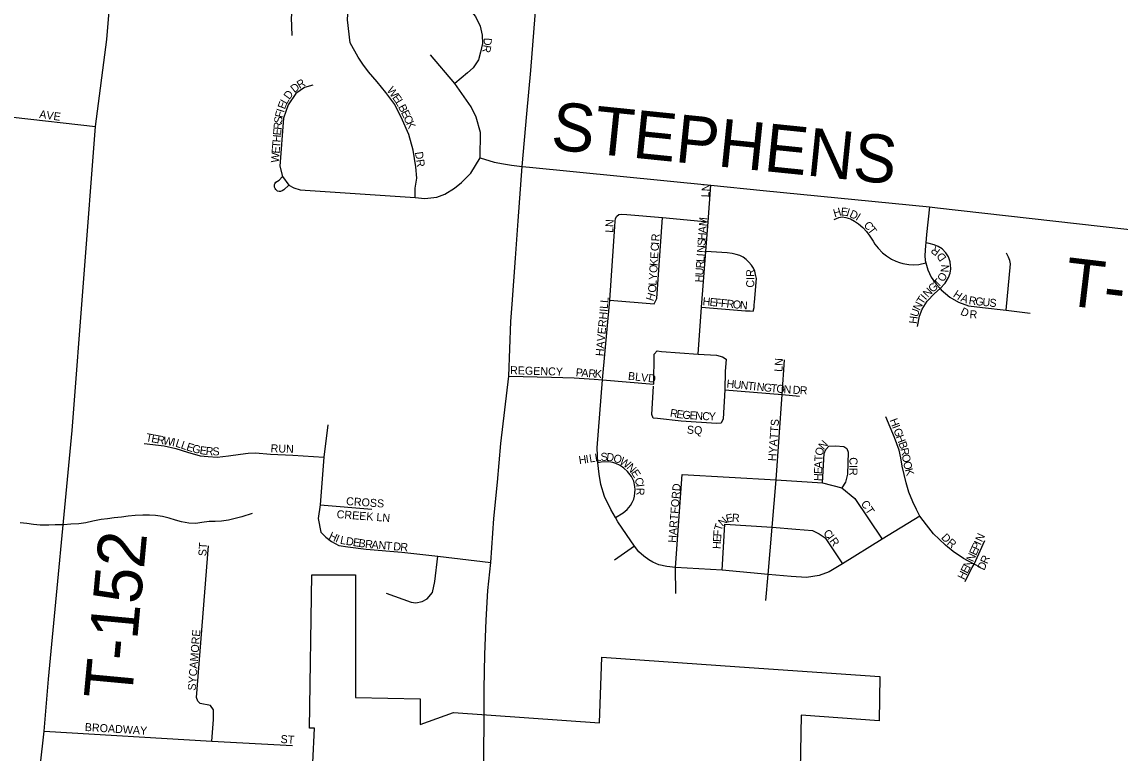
# Model space of a CAD drawing. Extents: x 1310247 to 1664935, y 284496 to 704931.
# Drawn here: x 1478771 to 1485632, y 484550 to 489120 of the extents above; entities that cross this region are included whole.
import ezdxf

# ---------------------------------------------------------------- set-up
doc = ezdxf.new("R2010")
doc.units = 0
for name, color, linetype in [('GM_P_State_Location', 7, 'Continuous'), ('GM_X_County_Subdivision_Text', 7, 'Continuous'), ('GM_X_Interstate_Shield', 7, 'Continuous'), ('GM_X_Major_Lake_Text', 7, 'Continuous'), ('GM_X_Minor_River_Text', 7, 'Continuous'), ('GM_X_State_Location', 7, 'Continuous'), ('GM_X_Township_Subdivision', 7, 'Continuous')]:
    doc.layers.add(name, color=color, linetype=linetype)

msp = doc.modelspace()

# ---------------------------------------------------------------- linework, layer by layer
at = {"layer": 'GM_X_County_Subdivision_Text'}
for points in [[(1478833.3, 483998.3), (1478911, 484686.8), (1478938.3, 485012.2), (1479085.4, 486565.2), (1479231.6, 488465.5), (1479301.4, 489011), (1479426.1, 490533.8)], [(1481634.8, 488270.5), (1481721.4, 488243), (1481779.5, 488232.1), (1481830.6, 488224.3), (1481896.7, 488216.2), (1481943.2, 488211.6)], [(1481943.2, 488211.6), (1483076.1, 488099.3), (1483402.3, 488067), (1484440.5, 487963.4), (1484490.8, 487958.4), (1485951.9, 487794.1), (1487377.7, 487632.8), (1488308.9, 487514.3), (1488786, 487462.6), (1489091.2, 487425.6)]]:
    msp.add_lwpolyline(points, dxfattribs=at)
at = {"layer": 'GM_X_Interstate_Shield'}
for points in [[(1481659.7, 484891.5), (1481659.8, 484951.8), (1481662.9, 485164.8), (1481672.3, 485380.9), (1481681.7, 485565.7), (1481700.5, 485741), (1481719.3, 486016.6), (1481743, 486242.3), (1481763.1, 486485.5), (1481812.3, 486906.5), (1481825.2, 487247.2), (1481835, 487356.5), (1481855.1, 487642.7), (1481871.5, 487875.9), (1481896.7, 488216.2), (1481925, 488546), (1481950.6, 488816.5), (1481984.1, 489239.5), (1482017.5, 489654.7), (1482052.9, 490048.2), (1482082.4, 490422.1), (1482102.1, 490668), (1482120.2, 490899.8)], [(1481860.4, 482849.6), (1481832.6, 482959.1), (1481766.5, 483237.6), (1481718.3, 483443.3), (1481689.4, 483591.1), (1481656.8, 483791.7), (1481652.6, 483885.5), (1481656.5, 484008.2), (1481654, 484367.2), (1481659.7, 484743.8), (1481659.7, 484891.5)]]:
    msp.add_lwpolyline(points, dxfattribs=at)
at = {"layer": 'GM_X_Major_Lake_Text'}
msp.add_lwpolyline([(1480588.6, 484489), (1480598.2, 484705.9), (1480567, 484705.9), (1480581.8, 485664), (1480854.8, 485664), (1480855, 484896.1), (1481258.3, 484889), (1481258.3, 484728.3), (1481466.6, 484802.7), (1482380.1, 484737.4), (1482394.4, 485149), (1483254.3, 485088.8), (1484131.2, 485027.5), (1484126.4, 484751.6), (1483638.6, 484785.7), (1483624.9, 483988.8)], dxfattribs=at)
at = {"layer": 'GM_X_Minor_River_Text'}
msp.add_lwpolyline([(1480209.9, 486047.8), (1480145.3, 486026.8), (1480103, 486015.5), (1480062.8, 486006.1), (1480018.5, 485998.8), (1479978.3, 485997.4), (1479940.2, 485996), (1479896, 485990.7), (1479857.8, 485985.3), (1479813.6, 485986), (1479767.7, 485994.7), (1479729.7, 486005.4), (1479691.8, 486018), (1479649.8, 486028.7), (1479605.8, 486035.4), (1479567.7, 486036), (1479525.6, 486036.7), (1479479.4, 486035.4), (1479435.2, 486030.1), (1479393, 486024.8), (1479346.8, 486019.5), (1479306.5, 486014.1), (1479266.3, 486008.7), (1479214, 485999.5), (1479169.7, 485988.2), (1479127.5, 485982.9), (1479077.3, 485979.7), (1479033.1, 485976.4), (1478978.9, 485975.2), (1478938.7, 485973.8), (1478884.6, 485974.7), (1478844.5, 485977.4), (1478802.5, 485984), (1478760.4, 485988.7)], dxfattribs=at)
at = {"layer": 'GM_X_State_Location'}
for points in [[(1480459.2, 489035.9), (1480456.2, 489148.1), (1480463.1, 489203.2), (1480467.1, 489264.1), (1480480.8, 489315.3), (1480507.4, 489358.6), (1480542.8, 489393), (1480586.1, 489411.7), (1480632.3, 489419.6), (1480688.4, 489417.6), (1480822.2, 489405.8), (1481266.9, 489374.3), (1481362.3, 489351.7), (1481434.1, 489313.3), (1481548.3, 489220.9), (1481604.3, 489154), (1481633.8, 489093.9), (1481646.6, 489036.9), (1481649.6, 488984.8), (1481636.8, 488930.6), (1481623, 488883.4), (1481589.6, 488833.2), (1481555.1, 488802.3), (1481475.4, 488735.8)], [(1481228.5, 488021.6), (1481228.5, 488080.5), (1481237.4, 488143.6), (1481231.5, 488214.4), (1481214.7, 488318.7), (1481188.2, 488416.1), (1481148.8, 488506.6), (1481100.6, 488603), (1481045.5, 488679.8), (1480990.4, 488745.7), (1480936.3, 488808.6), (1480901.9, 488855.9), (1480872.4, 488899.2), (1480822.2, 488989.7), (1480805.5, 489132.3), (1480822.2, 489405.8)], [(1480589.6, 488724.9), (1480535.7, 488709.2), (1480483, 488672.2), (1480433.7, 488601.5), (1480405.6, 488518.5), (1480383.2, 488217.9), (1480400, 488152.8), (1480439.3, 488099.5), (1480469, 488082.7), (1480509.9, 488069.8), (1481228.5, 488021.6), (1481288.5, 488015.7), (1481362.3, 488025.5), (1481413.5, 488044.2), (1481474.5, 488079.7), (1481517.7, 488116.1), (1481574.8, 488175.1), (1481634.8, 488270.5), (1481636.8, 488427.9), (1481608.3, 488524.3), (1481576.8, 488590.2), (1481475.4, 488735.8), (1481323.9, 488913.9)], [(1476895.4, 488497.4), (1476979.1, 488485.8), (1477070.9, 488505.3), (1477149.1, 488556.1), (1477237.1, 488585.5), (1477332.8, 488601.1), (1477432.5, 488608.9), (1477528.3, 488620.6), (1477602.6, 488638.2), (1477702.2, 488653.9), (1477823.4, 488655.8), (1478226, 488591.3), (1478717, 488524.3), (1479231.6, 488465.5)], [(1480439.3, 488099.5), (1480406.7, 488070.9), (1480397.2, 488064.1), (1480387.1, 488060.8), (1480378.1, 488060.8), (1480368.6, 488063), (1480363.5, 488066.4), (1480357.4, 488072), (1480352.9, 488078.2), (1480349.5, 488086), (1480349.5, 488095), (1480349.5, 488103.4), (1480350.6, 488108.5), (1480358.5, 488117.5), (1480378.1, 488131.5), (1480400, 488152.8)], [(1482995.3, 487044), (1483017.7, 487335.9), (1483044.4, 487684.4), (1483058.7, 487871.1), (1483076.1, 488099.3)], [(1484440.5, 487963.4), (1484422.9, 487790.5), (1484417.6, 487738.2), (1484416.1, 487723.3), (1484412.2, 487658.9), (1484415.1, 487628.7), (1484418, 487613.1), (1484430.7, 487570.2), (1484451.1, 487523.5), (1484483.3, 487480.6), (1484507, 487453.2), (1484514.5, 487444.5), (1484568.1, 487398.7), (1484622.7, 487367.5), (1484685.1, 487346.1), (1484771.8, 487335.3), (1484920.5, 487317.8), (1485069.1, 487300.3)], [(1484381.5, 486030), (1484146.4, 485887.4), (1483898.1, 485731.6), (1483815, 485682.6), (1483752.7, 485659), (1483673.4, 485647.6), (1483576.1, 485654.2), (1483433.1, 485666.5), (1483145.6, 485693), (1482854.9, 485710.4), (1482799.6, 485716.5), (1482749.6, 485726), (1482712.3, 485742.1), (1482687.2, 485757.1), (1482655.6, 485780.3), (1482624.9, 485808.1), (1482597.5, 485842.6), (1482548.2, 485915.2), (1482494.1, 485994.1), (1482479.1, 486021.5), (1482450.3, 486071.5), (1482411.5, 486154.1), (1482387, 486227.8), (1482377.5, 486292), (1482369.1, 486364.3), (1482364.4, 486458.1), (1482399.3, 486882), (1482443.2, 487379.7), (1482475, 487841.7), (1482477.2, 487873.5), (1482480, 487891.9), (1482487, 487904.8), (1482500.3, 487915.1), (1482519.4, 487918.8), (1482549.9, 487916.3), (1482772.4, 487898.4), (1483058.7, 487871.1)], [(1482443.2, 487379.7), (1482721.1, 487357.8), (1482737.3, 487390.1), (1482772.4, 487898.4)], [(1483845.9, 487885.4), (1483875.6, 487897.2), (1483895.9, 487901.4), (1483919.2, 487898.2), (1483946.9, 487889.7), (1483973.5, 487874.8), (1483996.9, 487857.8), (1484025.6, 487834.4), (1484048, 487809.9), (1484069.2, 487780.1), (1484088.4, 487749.3), (1484100.1, 487731.2), (1484120.3, 487706.7), (1484148, 487676.9), (1484172.4, 487656.7), (1484203.3, 487637.6), (1484230.9, 487623.8), (1484254.3, 487615.3), (1484275.6, 487608.9), (1484311.8, 487603.6), (1484339.4, 487601.4), (1484374.5, 487604.6), (1484418, 487613.1)], [(1483017.7, 487335.9), (1483291, 487313.7), (1483321.5, 487313.4), (1483339.3, 487311.9), (1483345, 487334.3), (1483346.5, 487350.7), (1483347.7, 487368.5), (1483359.5, 487515.3), (1483355.1, 487541.2), (1483349, 487561), (1483341, 487580.1), (1483329.3, 487600.4), (1483313.2, 487618.9), (1483296.5, 487635), (1483277.4, 487648.6), (1483257.1, 487659), (1483234.3, 487667), (1483207.7, 487673.2), (1483177.5, 487676.3), (1483044.4, 487684.4)], [(1484365.3, 487216.4), (1484378.3, 487280.3), (1484395.3, 487324.6), (1484426.6, 487374.2), (1484472.2, 487422.4), (1484507, 487453.2), (1484538.7, 487487.5), (1484560.8, 487522.7), (1484571.2, 487550.1), (1484575.1, 487577.5), (1484569.9, 487620.5), (1484559.5, 487650.5), (1484543.9, 487676.6), (1484520.4, 487701.3), (1484495.7, 487716.9), (1484469.6, 487727.4), (1484439.6, 487733.9), (1484417.6, 487738.2)], [(1484920.5, 487317.8), (1484947.9, 487607.8), (1484943.6, 487628), (1484935.1, 487649.3), (1484922.3, 487673.8)], [(1482718.2, 486856.4), (1482721.1, 487044), (1482739.3, 487063.6), (1482766.6, 487060.2), (1482995.3, 487044), (1483111.2, 487036.7), (1483147.8, 487026.5), (1483171.3, 487011.8), (1483165.4, 486935.5), (1483162.5, 486819.7), (1483151.5, 486639.3), (1483139, 486612.2), (1483109.7, 486610.1), (1482889.8, 486623.2), (1482741, 486640.1), (1482713.8, 486643.7), (1482707.2, 486666.5), (1482716.8, 486842.4)], [(1483419.1, 485503), (1483433.1, 485666.5), (1483458.5, 485961.6), (1483484, 486258.3), (1483521.1, 486791.2), (1483536.2, 487008)], [(1481812.3, 486906.5), (1482079.2, 486899.6)], [(1482079.2, 486899.6), (1482221.9, 486895.9), (1482345.7, 486886.2)], [(1482345.7, 486886.2), (1482399.3, 486882), (1482718.2, 486856.4)], [(1483162.5, 486819.7), (1483521.1, 486791.2), (1483629.6, 486780.9)], [(1484759.8, 485709.5), (1484719.6, 485731.1), (1484654.2, 485766.2), (1484588.9, 485810.2), (1484540.7, 485848.5), (1484501, 485886.8), (1484466.9, 485920.8), (1484423, 485976.1), (1484381.5, 486030), (1484360.6, 486071.1), (1484336.5, 486119.3), (1484312.4, 486180.3), (1484295.4, 486238.5), (1484282.6, 486290.9), (1484271.2, 486342), (1484262.7, 486395.9), (1484251.4, 486442.7), (1484223, 486522.1), (1484169.1, 486651.2)], [(1480681.8, 486601.9), (1480656.7, 486398.5), (1480633.8, 486101.1), (1480621.1, 486015.4), (1480638.6, 485930.5), (1480669, 485898.2), (1480704.3, 485871.7), (1480751, 485846.5), (1480807.7, 485837.7), (1480921.1, 485823.8), (1481145.5, 485806.1), (1481369, 485779.9), (1481700.5, 485741)], [(1479535.4, 486485.6), (1479659.6, 486470.5), (1479732.3, 486453.8), (1479806.6, 486429.6), (1479885.4, 486408.4), (1479933.9, 486402.3), (1479991.5, 486399.3), (1480062.7, 486406.9), (1480137, 486417.5), (1480185.5, 486425), (1480230.9, 486426.6), (1480323.4, 486417.5), (1480462.8, 486411.4), (1480656.7, 486398.5)], [(1483772.3, 486239.7), (1483782.4, 486422.9), (1483792.5, 486448.1), (1483812.6, 486467.9), (1483853, 486469.5), (1483906.8, 486466.6), (1483925.3, 486453.2), (1483933.7, 486431.3), (1483928.6, 486293.5), (1483916.9, 486243.1), (1483893.3, 486207.8)], [(1482479.1, 486021.5), (1482527.2, 486051.3), (1482553.2, 486072.9), (1482573.5, 486097.5), (1482584.3, 486115), (1482593.3, 486137.2), (1482598.5, 486155.6), (1482600.8, 486175.4), (1482601.8, 486195.2), (1482601.3, 486215), (1482594.7, 486248.1), (1482580.5, 486279.2), (1482554, 486310.3), (1482531, 486331.2), (1482509.5, 486346.1), (1482482.2, 486359.2), (1482463.8, 486365), (1482436.9, 486369.6), (1482390.2, 486367.7), (1482369.1, 486364.3)], [(1482854.9, 485707.8), (1482854.9, 485710.4), (1482896, 486291.7), (1483484, 486258.3)], [(1483484, 486258.3), (1483772.3, 486239.7), (1483893.3, 486207.8), (1483975.7, 486140.5), (1484146.4, 485887.4)], [(1480633.8, 486101.1), (1480957, 486074.7)], [(1483145.6, 485693), (1483162.5, 485979.6), (1483458.5, 485961.6), (1483605.9, 485949.8), (1483711, 485940.5), (1483752.2, 485920.4), (1483789.1, 485894.3), (1483898.1, 485731.6)], [(1479957.7, 484623.7), (1479967.1, 484759.4), (1479967.7, 484820), (1479949.7, 484845.9), (1479884.2, 484860.3), (1479870.5, 484874), (1479862.9, 484897.1), (1479936.9, 485844.5)], [(1482597.5, 485842.6), (1482474.3, 485755.3)], [(1484663.4, 485621.6), (1484684.6, 485666.2), (1484708.1, 485709.5), (1484719.6, 485731.1), (1484786.8, 485878.3)], [(1481046, 485548.9), (1481203.8, 485492), (1481232.7, 485488.8), (1481271.4, 485496.3), (1481303.6, 485514.5), (1481336.9, 485553.2), (1481350.8, 485621.9), (1481369, 485779.9)], [(1482856.7, 485547.7), (1482854.9, 485707.8)], [(1478911, 484686.8), (1479957.7, 484623.7), (1480461.5, 484596.1)]]:
    msp.add_lwpolyline(points, dxfattribs=at)

# ---------------------------------------------------------------- texts
at = {"layer": 'GM_P_State_Location'}
for s, rotation, p in [('D', 266.76318, (1481657.6, 489021.7)), ('R', 259.96669, (1481655.3, 488979.4)), ('D', 38.1069, (1480473.3, 488674.5)), ('R', 29.83523, (1480506.3, 488700.6)), ('W', 306.24119, (1481048.6, 488692.2)), ('D', 53.86013, (1480441.9, 488631)), ('E', 305.84258, (1481082.3, 488646.1)), ('I', 72.60165, (1480407.5, 488550.3)), ('E', 69.77648, (1480413.9, 488570.7)), ('L', 60.02472, (1480425.1, 488601.7)), ('L', 300.74819, (1481102.3, 488618.6)), ('B', 296.78229, (1481119.9, 488589.1)), ('E', 296.41843, (1481137.7, 488553.9)), ('AVE', 352.14337, (1478877.5, 488519.9)), ('S', 83.59342, (1480395.4, 488483.7)), ('F', 75.78484, (1480399.1, 488516.9)), ('C', 294.96849, (1481153.2, 488522.7)), ('E', 85.46092, (1480389.6, 488409.6)), ('R', 85.47233, (1480392.4, 488444.7)), ('K', 294.02242, (1481169.8, 488487)), ('T', 85.47971, (1480383.3, 488330.6)), ('H', 85.47052, (1480386.1, 488365.7)), ('W', 85.47233, (1480376, 488238.5)), ('E', 85.46092, (1480380.5, 488295.5)), ('DR', 278.53665, (1481226.3, 488305.2)), ('LN', 86.8215, (1483064.4, 488022.7)), ('H', 16.41667, (1483848, 487898.5)), ('E', 355.26812, (1483885.3, 487910.5)), ('I', 343.65239, (1483917.8, 487908)), ('M', 84.6555, (1483049.4, 487841.3)), ('D', 334.9699, (1483937, 487902.6)), ('I', 327.67963, (1483975.4, 487884.8)), ('L', 89.31696, (1482466, 487802)), ('N', 87.17906, (1482466.4, 487836.7)), ('A', 85.99567, (1483046.3, 487797.7)), ('C', 310.04811, (1484026.9, 487848)), ('T', 307.20873, (1484051.9, 487818.2)), ('R', 86.42686, (1482752.4, 487747.1)), ('S', 86.0003, (1483040.8, 487718.7)), ('H', 85.9751, (1483043.2, 487753.8)), ('E', 86.41804, (1482745.5, 487637.3)), ('C', 86.4282, (1482748.6, 487685.6)), ('I', 86.41275, (1482751, 487725.1)), ('N', 85.99567, (1483037.7, 487674.8)), ('R', 143.60394, (1484512.1, 487693.5)), ('K', 86.41275, (1482742.8, 487593.4)), ('R', 85.99049, (1483031, 487578.2)), ('L', 86.0003, (1483033.7, 487617.7)), ('I', 85.97357, (1483036.2, 487652.8)), ('D', 125.00494, (1484549.7, 487644.8)), ('Y', 86.41275, (1482737.3, 487505.5)), ('O', 86.43482, (1482740, 487549.5)), ('U', 85.99567, (1483027.9, 487534.3)), ('CIR', 90, (1483346, 487459)), ('O', 58.02519, (1484528, 487490.5)), ('N', 85.84899, (1484559.4, 487552.8)), ('O', 86.62644, (1482732.5, 487426.5)), ('L', 86.44582, (1482735.1, 487470.4)), ('H', 85.99691, (1483024.8, 487490.4)), ('G', 42.65008, (1484461.1, 487424.9)), ('T', 44.23063, (1484494.5, 487455.8)), ('H', 71.17105, (1482715.5, 487370.5)), ('T', 57.59793, (1484399, 487350)), ('I', 48.37008, (1484416.6, 487378)), ('N', 45.54094, (1484430.7, 487394)), ('H', 326.57665, (1484584.3, 487404.9)), ('A', 339.37833, (1484631.9, 487375.1)), ('R', 350.83005, (1484683.6, 487356.8)), ('HAVERHILL', 84.93655, (1482404.4, 487028.6)), ('H', 354.41772, (1483021.9, 487349.6)), ('E', 354.42828, (1483065.7, 487345.3)), ('F', 354.45292, (1483100.8, 487341.9)), ('F', 354.41719, (1483135.8, 487338.5)), ('R', 354.43394, (1483170.9, 487335)), ('O', 354.41772, (1483210.3, 487331.2)), ('N', 355.48809, (1483255.1, 487326.8)), ('N', 63.02437, (1484379.6, 487311.8)), ('G', 354.03366, (1484725.7, 487350.1)), ('U', 354.30474, (1484769.7, 487345.5)), ('S', 354.28125, (1484813.5, 487341.1)), ('H', 83.31952, (1484362.4, 487230.7)), ('U', 72.16625, (1484367, 487271.9)), ('D', 333.83568, (1484629.8, 487293)), ('R', 357.36082, (1484690.5, 487268.1)), ('LN', 86.82218, (1483522, 486931.5)), ('REGENCY', 358.2653, (1481820.1, 486918.4)), ('P', 355.76058, (1482229.8, 486905.2)), ('A', 355.73373, (1482264.9, 486902.6)), ('R', 355.74758, (1482308.7, 486899.3)), ('K', 355.75902, (1482348.3, 486896.4)), ('BLVD', 353.83361, (1482555.6, 486883.1)), ('H', 354.30681, (1483171.5, 486834.8)), ('U', 354.28506, (1483215.3, 486830.4)), ('N', 354.30474, (1483259.1, 486826)), ('T', 354.30843, (1483302.9, 486821.7)), ('I', 354.30681, (1483337.9, 486818.2)), ('N', 354.28506, (1483359.8, 486816)), ('G', 354.29273, (1483403.6, 486811.6)), ('T', 354.28612, (1483447.4, 486807.3)), ('O', 354.73306, (1483482.8, 486803.7)), ('N', 356.41233, (1483528.2, 486799.6)), ('D', 356.74136, (1483585.6, 486796)), ('R', 356.71912, (1483629.5, 486793.5)), ('R', 350.21429, (1482817.2, 486652.8)), ('E', 351.78195, (1482857.7, 486645.9)), ('G', 355.42061, (1482896, 486640.4)), ('E', 356.50655, (1482940.9, 486636.9)), ('N', 356.63739, (1482976.1, 486634.7)), ('C', 356.62213, (1483020, 486632.1)), ('Y', 358.59662, (1483061.5, 486629.7)), ('SQ', 356.82219, (1482924.4, 486546.5)), ('HYATTS', 85.84265, (1483482.4, 486372.9)), ('H', 290.7786, (1484191.4, 486630.8)), ('I', 290.79565, (1484207, 486589.6)), ('T', 349.36524, (1479542.2, 486500.3)), ('E', 349.36524, (1479576.8, 486493.8)), ('R', 349.35201, (1479611.4, 486487.3)), ('W', 349.37572, (1479650.4, 486480)), ('I', 349.35886, (1479706.6, 486469.4)), ('G', 290.80165, (1484214.8, 486569)), ('H', 290.7786, (1484230.4, 486527.9)), ('L', 343.29291, (1479726.8, 486465.7)), ('L', 340.70093, (1479760, 486455.7)), ('E', 342.2783, (1479794.6, 486443.6)), ('G', 345.41838, (1479831, 486432.1)), ('E', 351.16849, (1479879, 486419.9)), ('R', 355.49597, (1479917.9, 486414)), ('S', 359.5809, (1479961.3, 486410.7)), ('RUN', 358.02611, (1480324.1, 486430)), ('O', 76.8383, (1483772.9, 486404.9)), ('N', 49.11424, (1483780, 486442.1)), ('B', 289.66363, (1484246, 486487)), ('R', 282.90544, (1484258.8, 486451.2)), ('H', 8.909, (1482253.8, 486355.1)), ('I', 8.86581, (1482297.3, 486361.9)), ('L', 8.9159, (1482319.1, 486365.3)), ('L', 8.88741, (1482353.9, 486370.7)), ('S', 1.50312, (1482386.9, 486376)), ('D', 353.60429, (1482420.3, 486377)), ('O', 343.21703, (1482461.7, 486372.6)), ('W', 326.63638, (1482500.4, 486361.5)), ('T', 88.24834, (1483772.1, 486372.3)), ('CIR', 270, (1483941.2, 486398.6)), ('O', 280.12698, (1484267.6, 486413.2)), ('N', 313.40758, (1482545.8, 486332)), ('E', 302.63674, (1482574.5, 486302)), ('E', 88.2594, (1483769.7, 486293.1)), ('A', 88.25105, (1483770.8, 486328.3)), ('O', 282.77802, (1484275.8, 486367.4)), ('K', 286.33367, (1484286.4, 486321.2)), ('C', 286.44573, (1482597.6, 486263.8)), ('H', 88.25105, (1483768.4, 486249.2)), ('I', 276.65877, (1482608.4, 486228)), ('R', 267.98405, (1482610.8, 486208.2)), ('HARTFORD', 85.42572, (1482857.6, 485862.6)), ('CROSS', 356.09659, (1480795.3, 486100)), ('CT', 303.68671, (1484010.1, 486109)), ('CREEK LN', 355.7938, (1480736.2, 486018.6)), ('E', 12.36713, (1483174.8, 485989.2)), ('R', 357.39879, (1483205.8, 485996.4)), ('T', 72.2405, (1483141.3, 485934.9)), ('N', 42.30382, (1483148.4, 485962.7)), ('H', 335.85996, (1480684, 485889.3)), ('I', 337.28653, (1480725.4, 485870.8)), ('L', 348.36926, (1480755.8, 485859.2)), ('D', 351.06953, (1480792.8, 485851.6)), ('E', 87.20885, (1483138.5, 485868)), ('F', 87.20885, (1483140.2, 485903.2)), ('C', 315.92737, (1483774, 485918.4)), ('I', 306.72133, (1483801, 485892.4)), ('R', 305.44169, (1483814, 485875)), ('D', 312.91323, (1484511, 485894.2)), ('N', 65.76865, (1484770.1, 485865)), ('ST', 86.17432, (1479922.8, 485778.8)), ('E', 351.32038, (1480836.5, 485844.7)), ('B', 351.45865, (1480871.4, 485839.4)), ('R', 353.98043, (1480913, 485833.2)), ('A', 355.35315, (1480953.7, 485828.9)), ('N', 355.37564, (1480997.6, 485825.4)), ('T', 355.37705, (1481041.4, 485821.8)), ('D', 355.38338, (1481089.7, 485818)), ('R', 355.38154, (1481133.5, 485814.4)), ('H', 87.20885, (1483136.3, 485824.1)), ('R', 320.83937, (1484546.4, 485856.9)), ('E', 65.78612, (1484732.2, 485780.7)), ('P', 65.79342, (1484746.7, 485812.8)), ('I', 65.76228, (1484761.1, 485844.9)), ('N', 63.97889, (1484693.9, 485699.6)), ('N', 65.48769, (1484713.8, 485740.4)), ('R', 66.36815, (1484801.4, 485728.3)), ('E', 63.4585, (1484678, 485667.7)), ('D', 65.62477, (1484782.9, 485687.6)), ('H', 63.46427, (1484658.4, 485628.3)), ('SYCAMORE', 85.54398, (1479856.8, 484938.5)), ('BROADWAY', 356.51262, (1479162.8, 484687.6)), ('ST', 356.42537, (1480386, 484612.8))]:
    msp.add_text(s, height=50, rotation=rotation, dxfattribs=at).set_placement(p)
at = {"layer": 'GM_X_Township_Subdivision'}
for s, rotation, p in [('STEPHENS', 354.16521, (1482069.9, 488324.4)), ('T-158', 353.22375, (1485274, 487351.1)), ('T-152', 84.6527, (1479456.3, 484876.1))]:
    msp.add_text(s, height=300, rotation=rotation, dxfattribs=at).set_placement(p)

doc.saveas('drawing.dxf')
